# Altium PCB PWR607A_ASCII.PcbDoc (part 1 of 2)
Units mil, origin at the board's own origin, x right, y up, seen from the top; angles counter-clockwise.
Board outline 5200 x 2850 mil, 4 copper layers (Top Layer, MidLayer1, MidLayer2, Bottom Layer), stack 61.6 mil thick; 153 components, 65 nets, 324 pads, 227 vias.
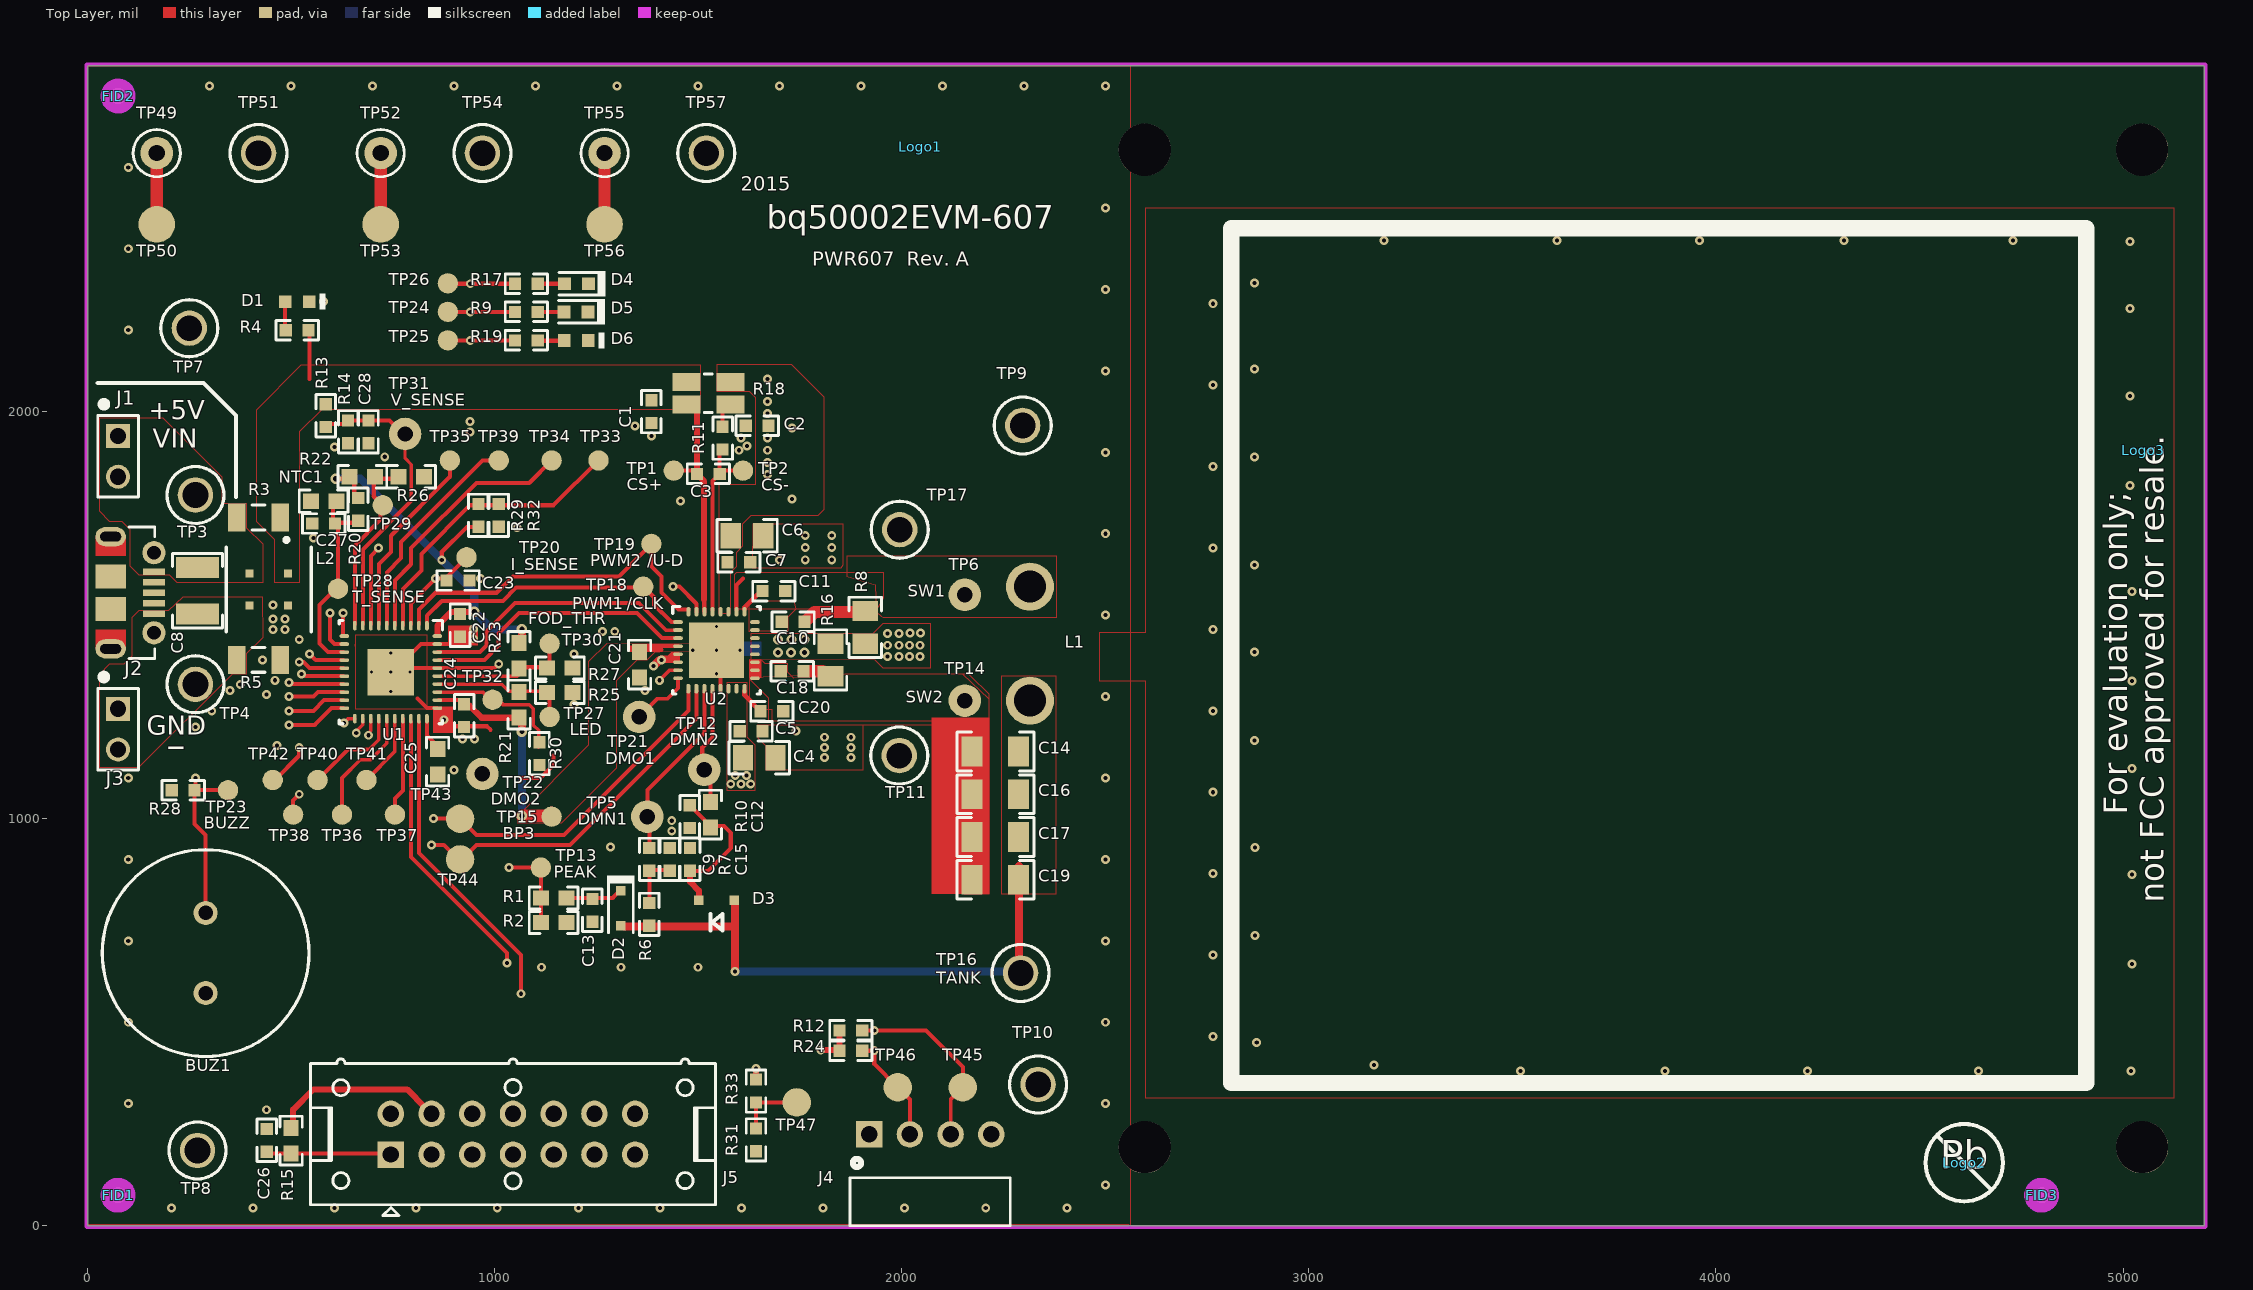
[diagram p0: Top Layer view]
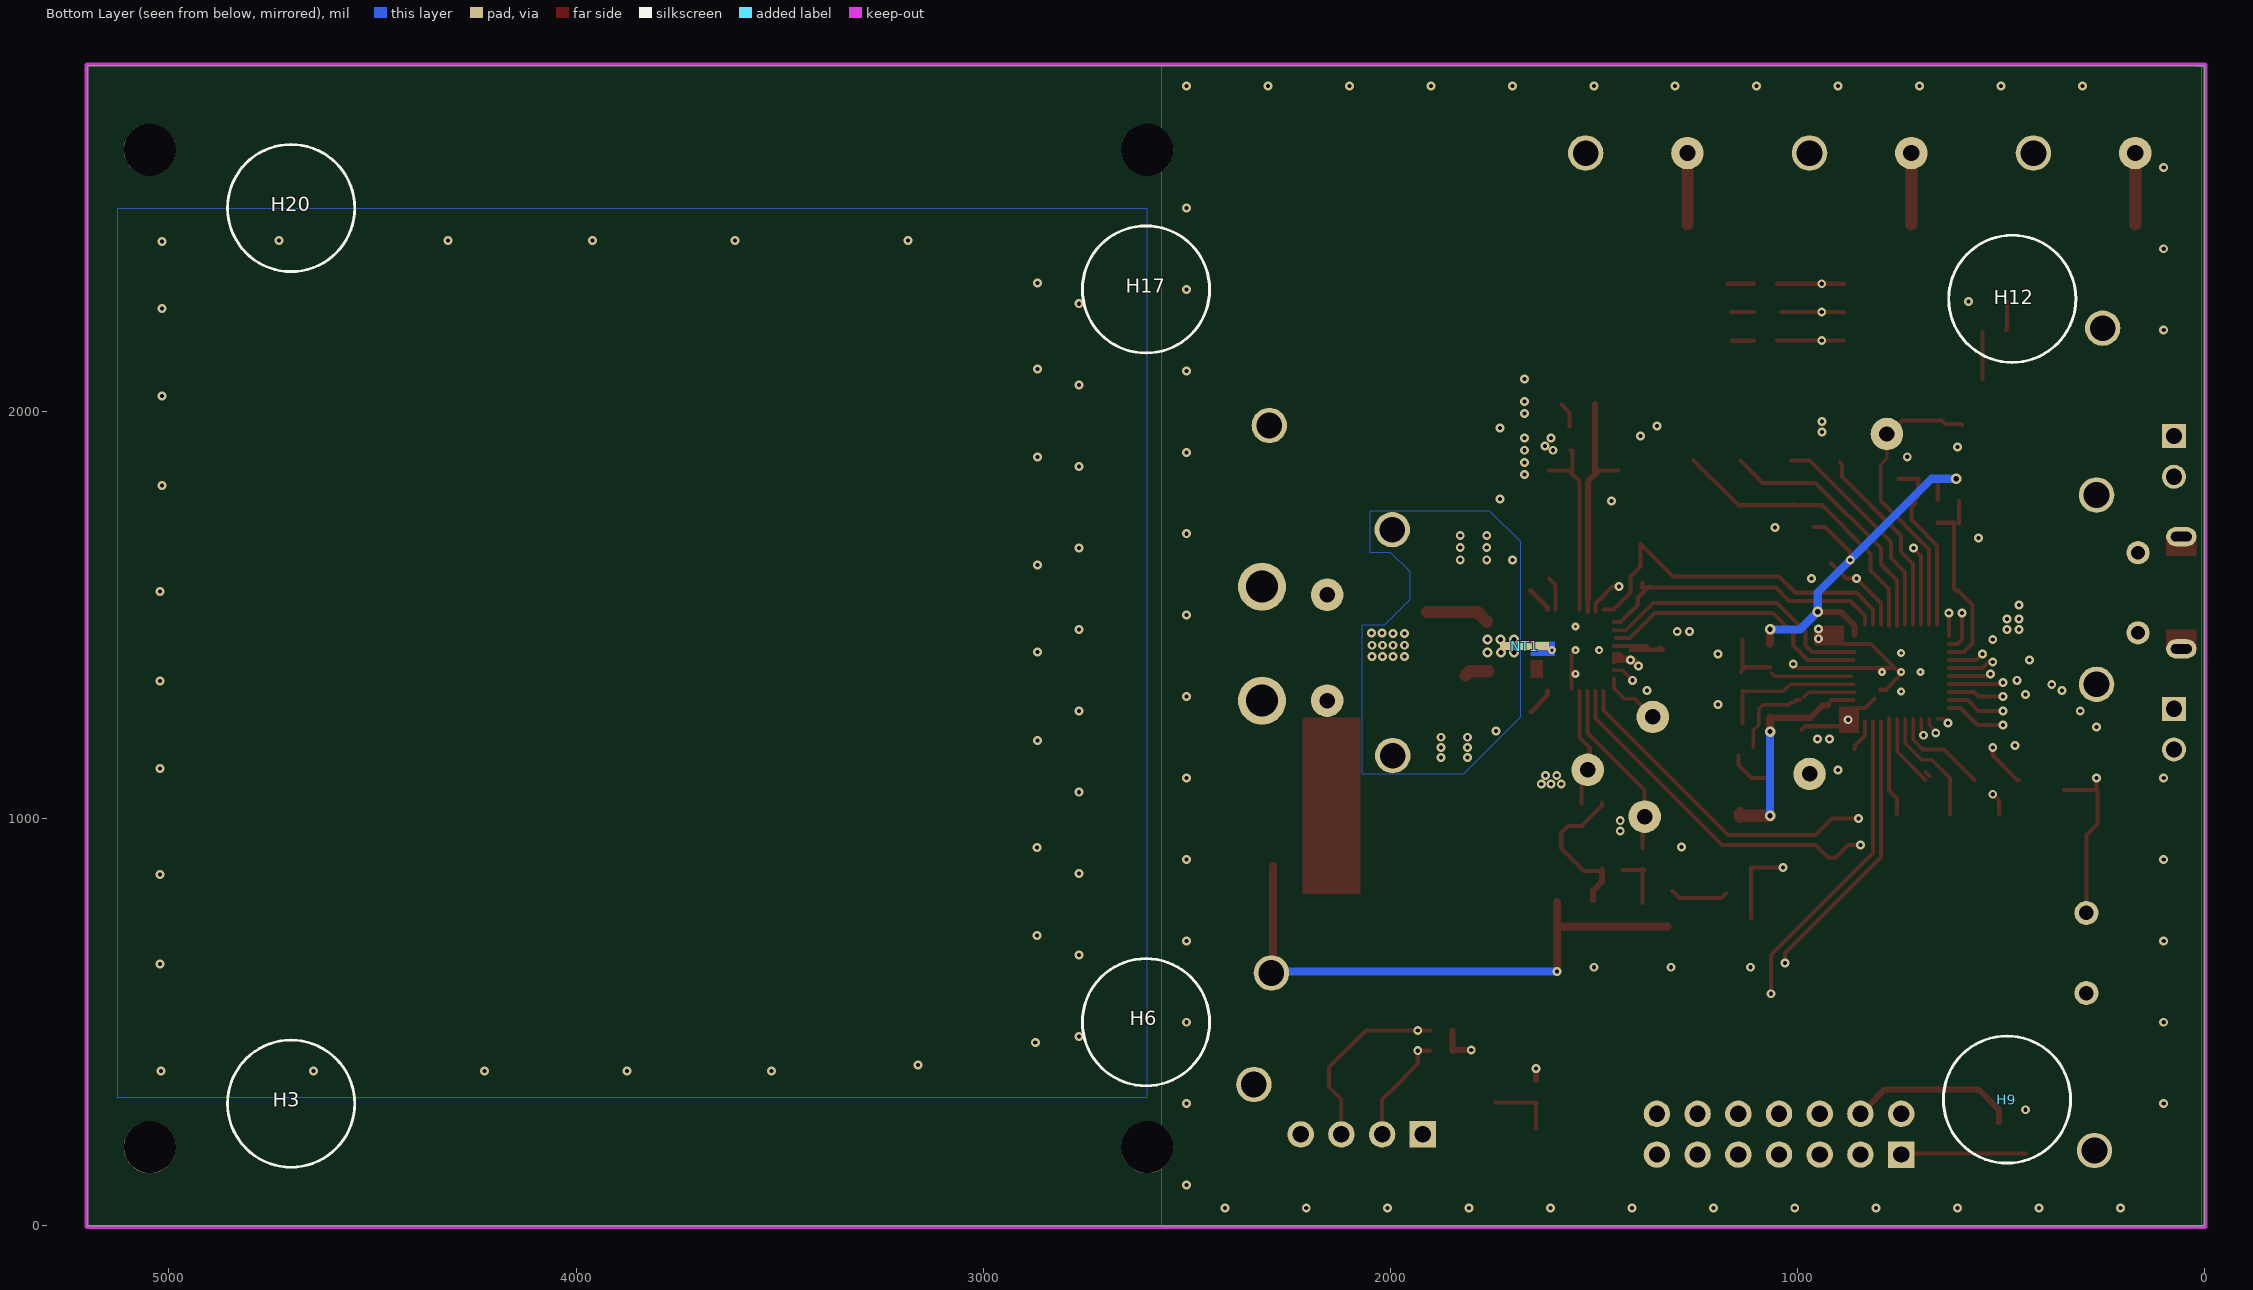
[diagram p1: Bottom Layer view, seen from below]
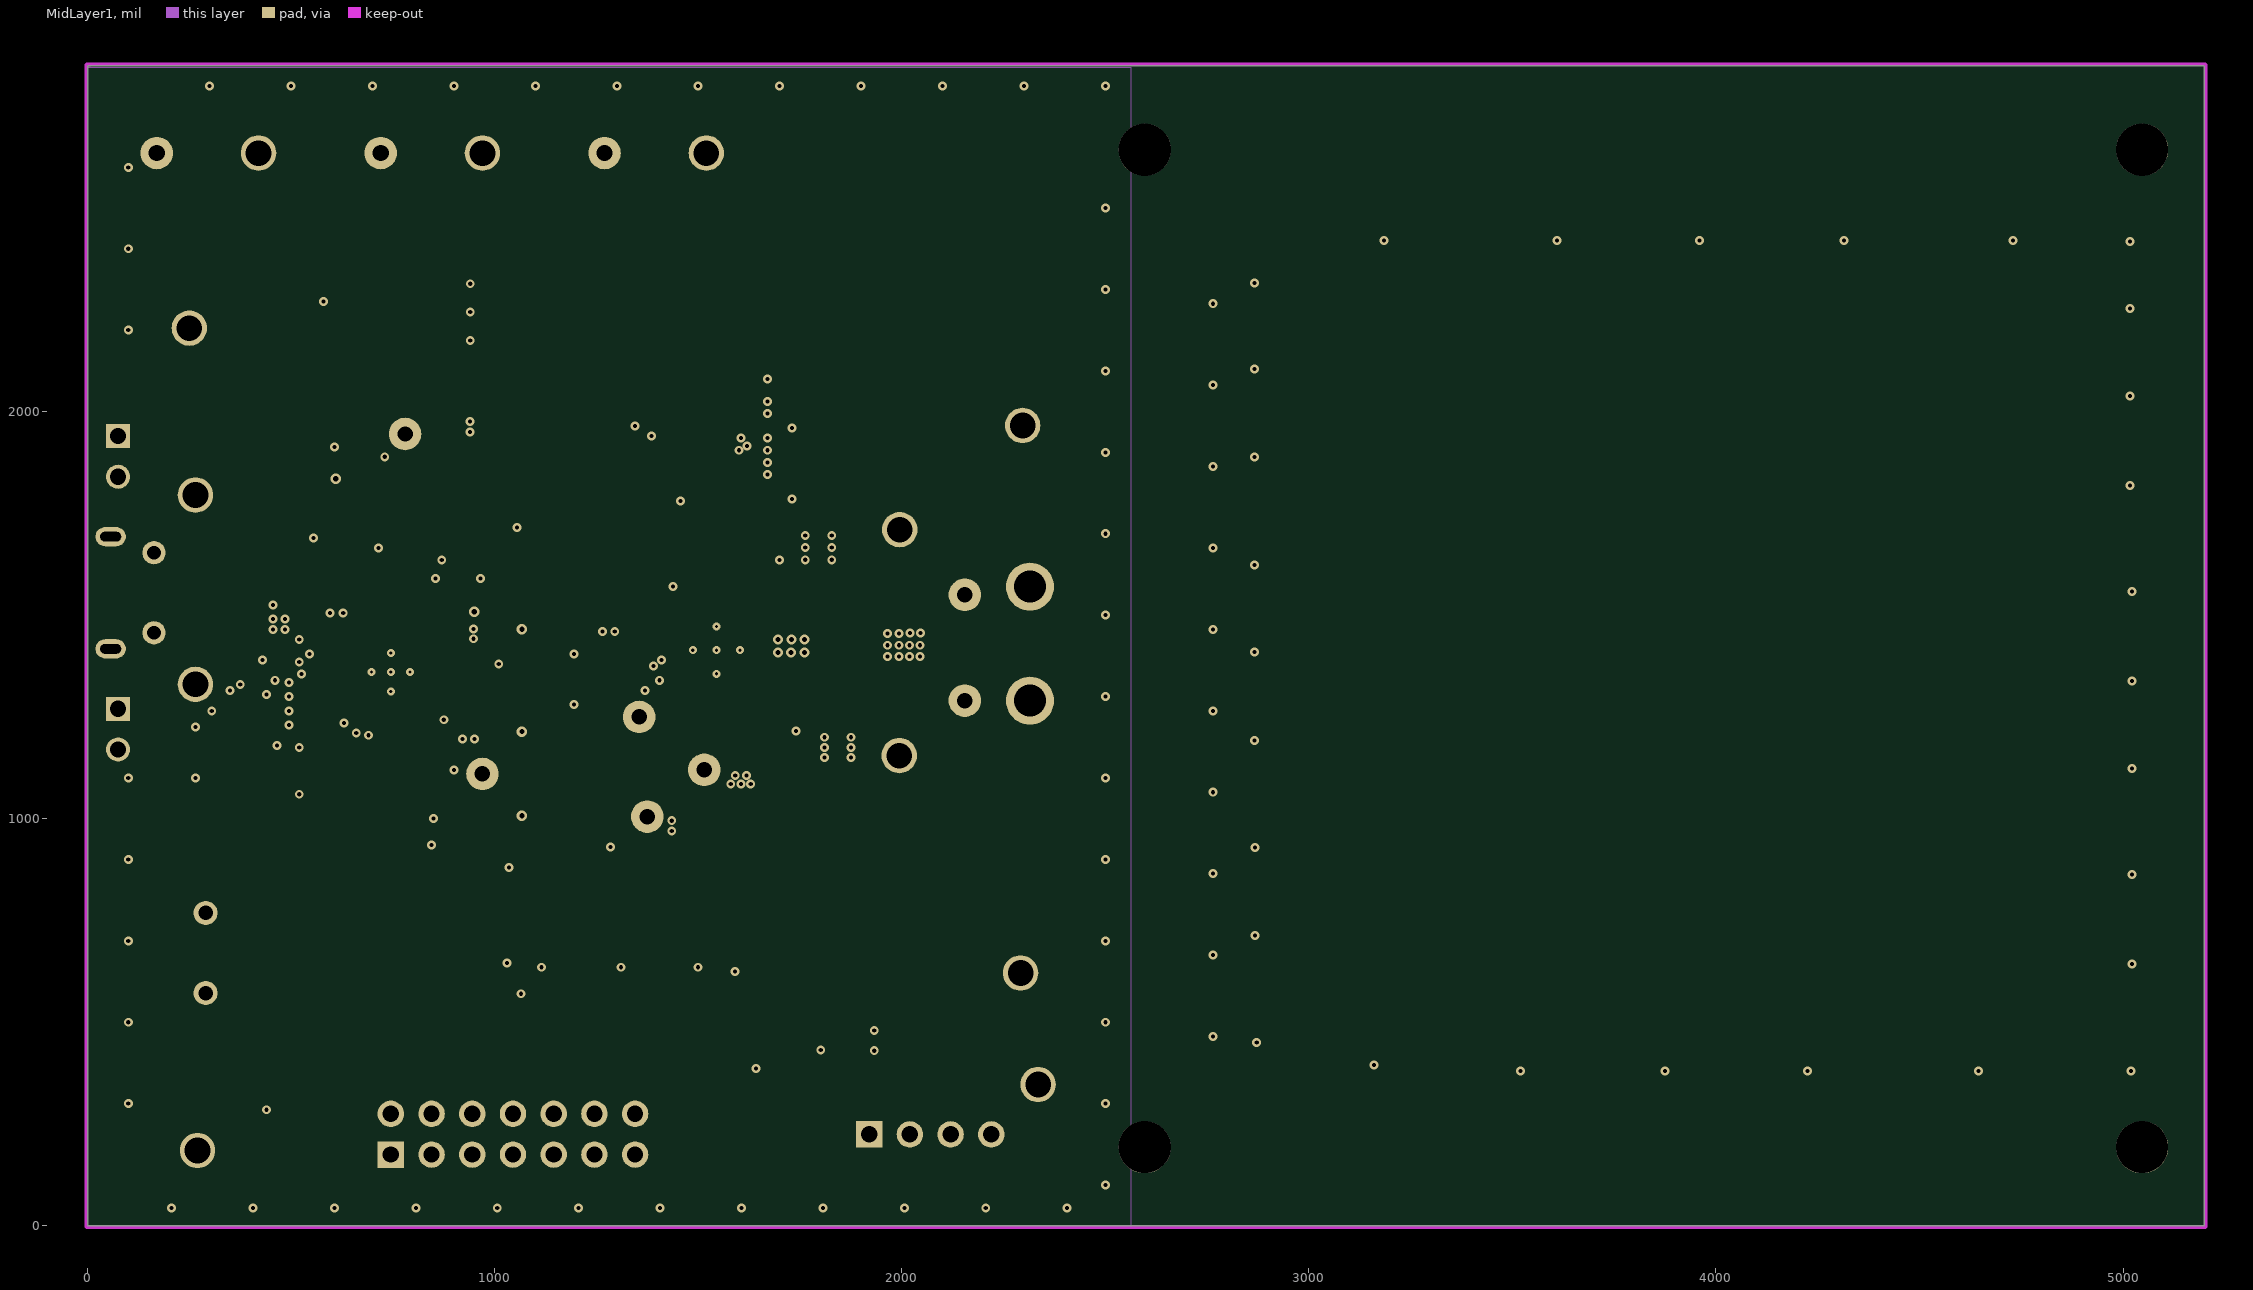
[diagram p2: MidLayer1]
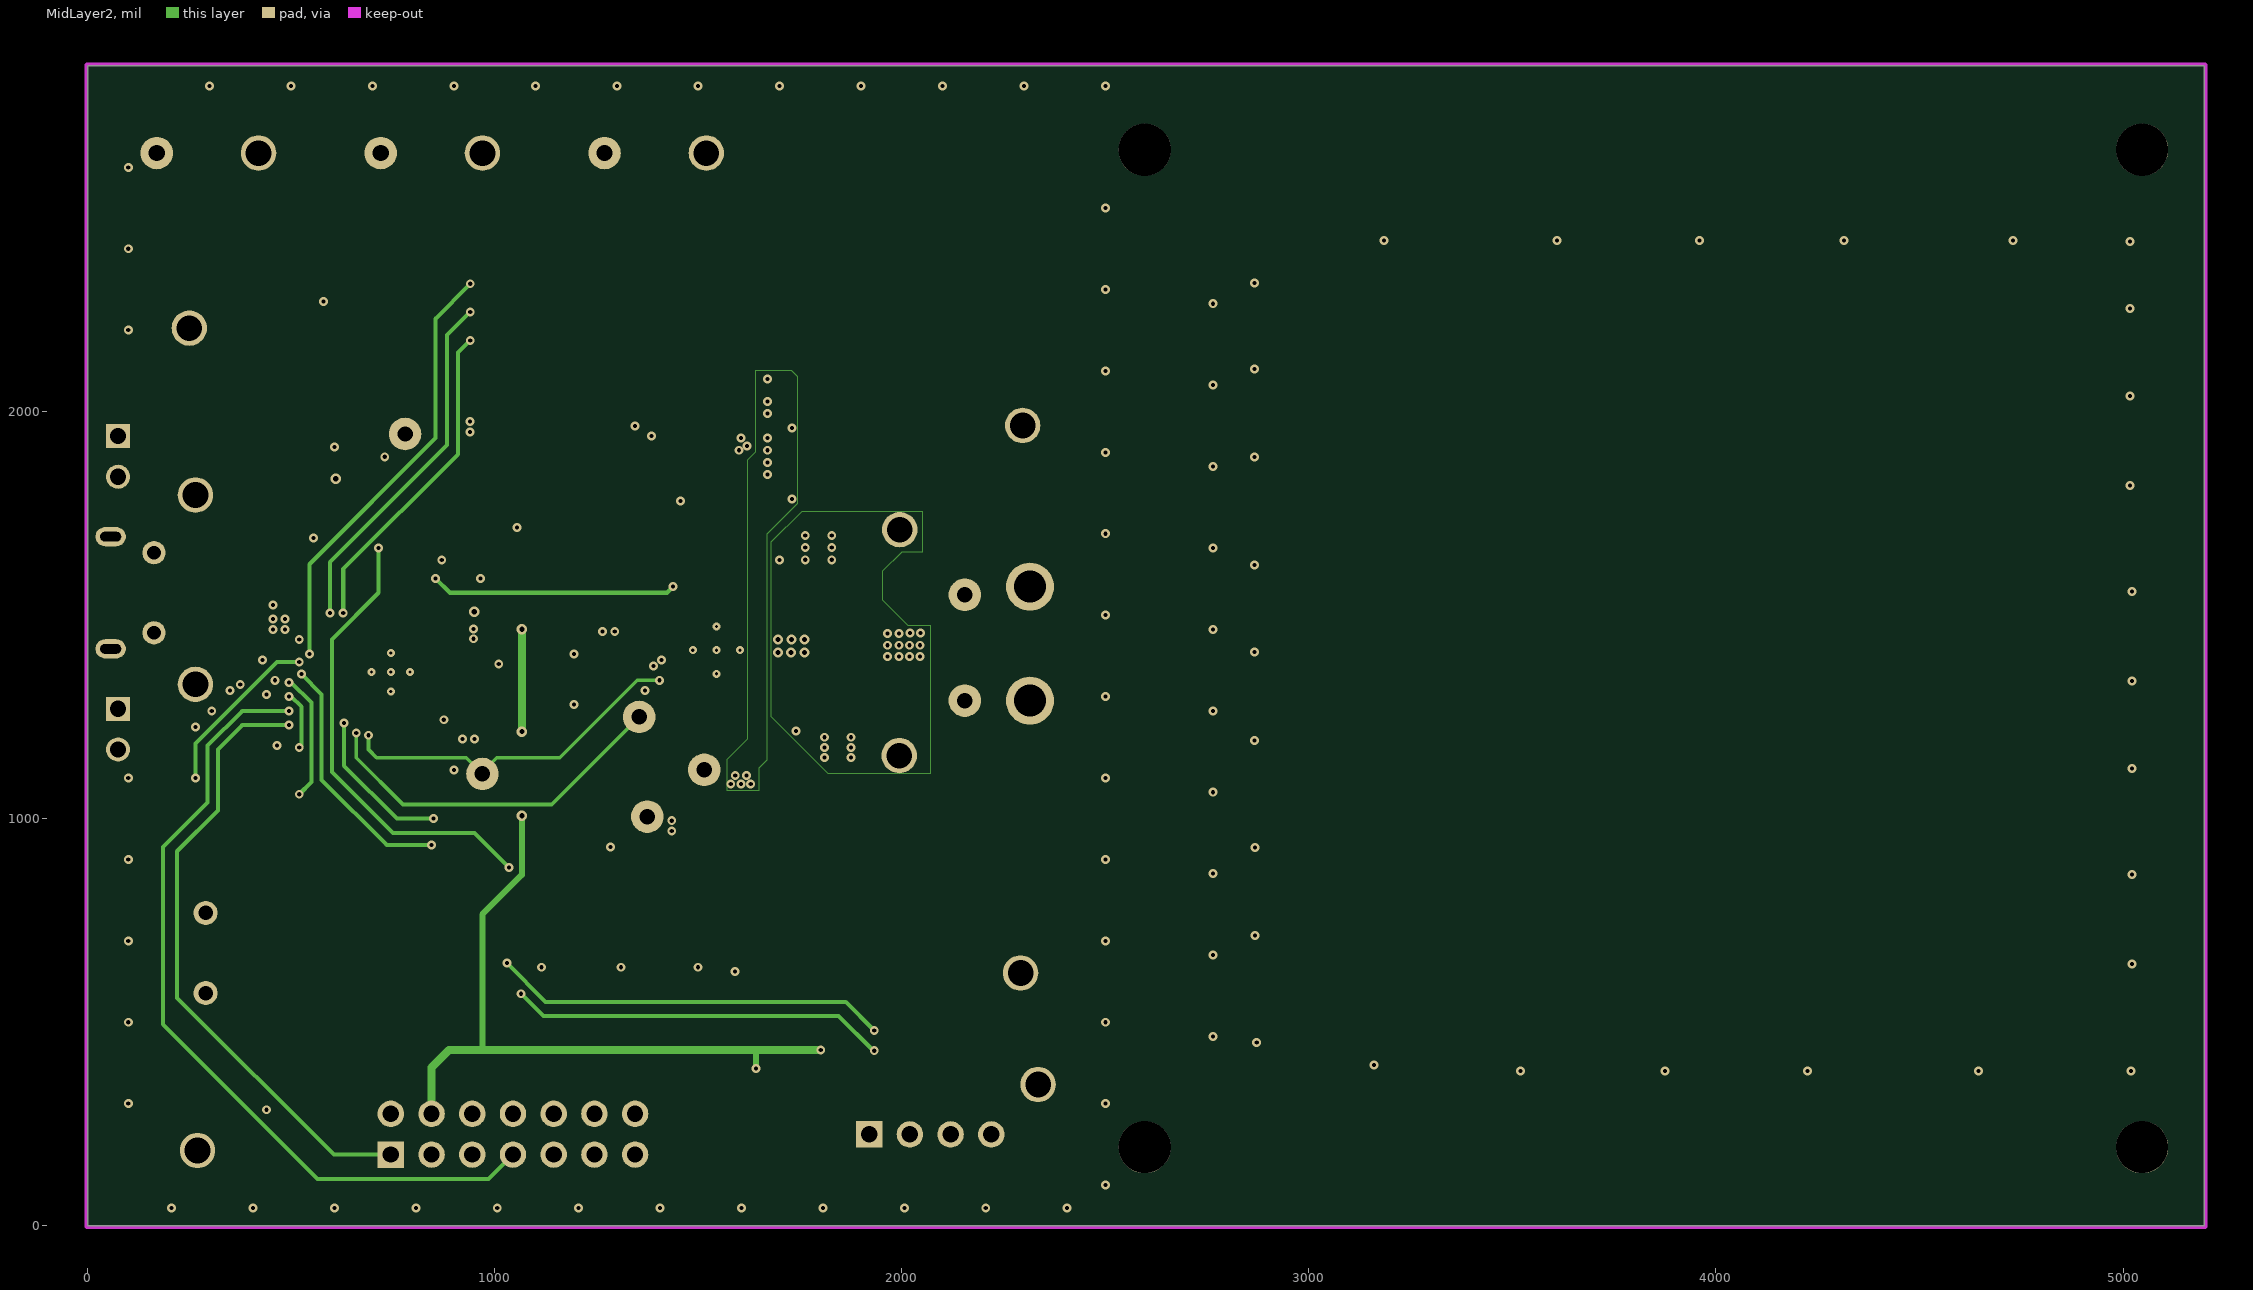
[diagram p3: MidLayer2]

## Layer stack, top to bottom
Top Solder: solder mask 0.4, Solder Resist, Dk 3.5
Top Layer: signal copper 1.4
Dielectric1: core 18, FR-4 High Tg, Dk 4.8
MidLayer1: signal copper 1.4
Dielectric2: prepreg 20, FR-4 High Tg, Dk 4.8
MidLayer2: signal copper 1.4
Dielectric3: core 18, FR-4 High Tg, Dk 4.8
Bottom Layer: signal copper 1.4
Bottom Solder: solder mask 0.4, Solder Resist, Dk 3.5

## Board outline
0,0 0,2850 5200,2850 5200,0

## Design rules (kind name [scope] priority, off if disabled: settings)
AcuteAngle [All] p0: scope1count=1 scope1_0_kind=Board scope1_0_value=Board scope2count=1 scope2_0_kind=Board scope2_0_value=Board commentlength=0 minimum=4.50000000000000E+0001
AcuteAngle [All] p1: minimum=4.50000000000000E+0001 checktracksonly=FALSE
AssemblyTestPointUsage [All] p0 off: scope1count=1 scope1_0_kind=Board scope1_0_value=Board scope2count=1 scope2_0_kind=Board scope2_0_value=Board commentlength=0
AssemblyTestPointUsage [All] p1 off: valid=2
AssemblyTestpoint [All] p0 off: scope1count=1 scope1_0_kind=Board scope1_0_value=Board scope2count=1 scope2_0_kind=Board scope2_0_value=Board commentlength=0
AssemblyTestpoint [All] p1 off: testpointundercomponent=TRUE minsize=40 maxsize=100 preferedsize=60 minholesize=0 maxholesize=40 preferedholesize=32 testpointgrid=1 usegrid=TRUE gridtolerance=0.01 allowsidetop=TRUE allowsidebottom=TRUE
Clearance Clearance_BoardEdge_MountingHoles [All] p0 off: scope1count=1 scope1_0_kind=Board scope1_0_value=Board scope2count=1 scope2_0_kind=Board scope2_0_value=Board commentlength=48 gap=40 // Protel DXP Scope 2 Expression Was: IsKeepOut
Clearance Clearance_BoardEdge_Poly [All] p0 off: scope1count=1 scope1_0_kind=Board scope1_0_value=Board scope2count=1 scope2_0_kind=Board scope2_0_value=Board commentlength=48 gap=25 // Protel DXP Scope 2 Expression Was: IsKeepOut
Clearance Clearance_BoardEdge [All] p0 off: scope1count=1 scope1_0_kind=Board scope1_0_value=Board scope2count=1 scope2_0_kind=Board scope2_0_value=Board commentlength=48 gap=25 // Protel DXP Scope 2 Expression Was: IsKeepOut
Clearance [All] p0: scope1count=1 scope1_0_kind=Board scope1_0_value=Board scope2count=1 scope2_0_kind=Board scope2_0_value=Board commentlength=0 gap=7.8
Clearance Clearance_Poly [All] p0 off: scope1count=1 scope1_0_kind=Board scope1_0_value=Board scope2count=1 scope2_0_kind=Board scope2_0_value=Board commentlength=48 gap=10 // Protel DXP Scope 1 Expression Was: InPolygon
Clearance Clearance_J1 [All] p0 off: scope1count=1 scope1_0_kind=Board scope1_0_value=Board scope2count=1 scope2_0_kind=Board scope2_0_value=Board commentlength=48 gap=15 // Protel DXP Scope 2 Expression Was: iskeepout
Clearance Clearance_GND_poly [All] p0 off: scope1count=1 scope1_0_kind=Board scope1_0_value=Board scope2count=1 scope2_0_kind=Board scope2_0_value=Board commentlength=62 gap=15 // Protel DXP Scope 1 Expression Was: inpoly and innet('GND')
Clearance Clearance_J1 [OnCopper and InComponent('J1') vs iskeepout] p1: gap=15
Clearance Clearance_BoardEdge_MountingHoles [OnCopper and InComponentClass('Mounting Holes') vs IsKeepOut] p2: gap=40
Clearance Clearance_BoardEdge_Poly [OnCopper and InPoly vs IsKeepOut] p3: gap=25
Clearance Clearance_BoardEdge [OnCopper and Not InComponentClass('Logo') and not InComponentClass('FiducialMark') and not InRegion(1000,500,4000,800) and Not IsKeepout vs IsKeepOut] p4: gap=25
Clearance Clearance_GND_poly [inpoly and innet('GND')] p5: gap=15
Clearance Clearance_Poly [InPolygon] p6: gap=10
Clearance [All] p7: gap=7.8
ComponentClearance ComponentClearance_Logo [All] p0 off: scope1count=1 scope1_0_kind=ComponentClass scope1_0_value=Logo scope2count=1 scope2_0_kind=Board scope2_0_value=Board commentlength=0 gap=50 collisioncheckmode=3
ComponentClearance ComponentClearance_ScrewToNut [All] p0 off: scope1count=1 scope1_0_kind=Board scope1_0_value=Board scope2count=1 scope2_0_kind=Board scope2_0_value=Board commentlength=71 gap=5 collisioncheckmode=3 // Protel DXP Scope 2 Expression Was: (HasFootprint('Keystone_1902C'))
ComponentClearance ComponentClearance_MountingHoles [All] p0 off: scope1count=1 scope1_0_kind=ComponentClass scope1_0_value="Mounting Holes" scope2count=1 scope2_0_kind=Board scope2_0_value=Board commentlength=0 gap=250 collisioncheckmode=3
ComponentClearance ComponentClearance_SmallPassives [All] p0 off: scope1count=1 scope1_0_kind=Board scope1_0_value=Board scope2count=1 scope2_0_kind=Board scope2_0_value=Board commentlength=508 gap=20 collisioncheckmode=3 // Protel DXP Scope 2 Expression Was: HasFootprint('0201*') or HasFootprint('0402*') or HasFootprint('0508') or HasFootprint('0603*') or HasFootprint('0612') or HasFootprint('0805*') or HasFootprint('0815*') or HasFootprint('0830*') or HasFootprint('1206*') or HasFootprint('1210*') or HasFootprint('1808*') or HasFootprint('1812*') or HasFootprint('1825*') or HasFootprint('2010*') or HasFootprint('2220*') or HasFootprint('2225*') or HasFootprint('2512*') or HasFootprint('2728*') or HasFootprint('3518*')
ComponentClearance ComponentClearance_THtoSMT [All] p0 off: scope1count=1 scope1_0_kind=Board scope1_0_value=Board scope2count=1 scope2_0_kind=Board scope2_0_value=Board commentlength=53 gap=100 collisioncheckmode=3 // Protel DXP Scope 2 Expression Was: IsSMTComponent
ComponentClearance ComponentClearance_THtoTH [All] p0 off: scope1count=1 scope1_0_kind=Board scope1_0_value=Board scope2count=1 scope2_0_kind=Board scope2_0_value=Board commentlength=54 gap=118.11 collisioncheckmode=3 // Protel DXP Scope 2 Expression Was: IsThruComponent
ComponentClearance [All] p0 off: scope1count=1 scope1_0_kind=Board scope1_0_value=Board scope2count=1 scope2_0_kind=Board scope2_0_value=Board commentlength=0 gap=40 collisioncheckmode=3
ComponentClearance ComponentClearance_Logo [InComponentClass('Logo')] p1 off: gap=50 collisioncheckmode=3 verticalgap=10 showdistances=FALSE
ComponentClearance ComponentClearance_ScrewToNut [(HasFootprint('NY PMS 440 0025 PH')) vs (HasFootprint('Keystone_1902C'))] p2 off: gap=5 collisioncheckmode=3 verticalgap=10 showdistances=FALSE
ComponentClearance ComponentClearance_MountingHoles [InComponentClass('Mounting Holes')] p3 off: gap=250 collisioncheckmode=3 verticalgap=100000 showdistances=FALSE
ComponentClearance ComponentClearance_SmallPassives [HasFootprint('0201*') or HasFootprint('0402*') or HasFootprint('0508') or HasFootprint('0603*') or HasFootprint('0612') or HasFootprint('0805*') or HasFootprint('0815*') or HasFootprint('0830*') or HasFootprint('1206*') or HasFootprint('1210*') or HasFootprint('1808*') or HasFootprint('1812*') or HasFootprint('1825*') or HasFootprint('2010*') or HasFootprint('2220*') or HasFootprint('2225*') or HasFootprint('2512*') or HasFootprint('2728*') or HasFootprint('3518*') vs HasFootprint('0201*') or HasFootprint('0402*') or HasFootprint('0508') or HasFootprint('0603*') or HasFootprint('0612') or HasFootprint('0805*') or HasFootprint('0815*') or HasFootprint('0830*') or HasFootprint('1206*') or HasFootprint('1210*') or HasFootprint('1808*') or HasFootprint('1812*') or HasFootprint('1825*') or HasFootprint('2010*') or HasFootprint('2220*') or HasFootprint('2225*') or HasFootprint('2512*') or HasFootprint('2728*') or HasFootprint('3518*')] p4 off: gap=20 collisioncheckmode=3 verticalgap=10 showdistances=FALSE
ComponentClearance ComponentClearance_THtoSMT [IsThruComponent vs IsSMTComponent] p5 off: gap=100 collisioncheckmode=3 verticalgap=30 showdistances=FALSE
ComponentClearance ComponentClearance_THtoTH [IsThruComponent vs IsThruComponent] p6 off: gap=118.11 collisioncheckmode=3 verticalgap=30 showdistances=FALSE
ComponentClearance [All] p7 off: gap=40 collisioncheckmode=3 verticalgap=10 showdistances=FALSE
DiffPairsRouting [All] p0: scope1count=1 scope1_0_kind=Board scope1_0_value=Board scope2count=1 scope2_0_kind=Board scope2_0_value=Board commentlength=0
DiffPairsRouting [All] p1: maxlimit=100 minlimit=10 mostfreqgap=10 toplayer_minwidth=15 toplayer_maxwidth=15 toplayer_prefwidth=15 midlayer1_minwidth=15 midlayer1_maxwidth=15 midlayer1_prefwidth=15 midlayer2_minwidth=15 midlayer2_maxwidth=15 midlayer2_prefwidth=15 bottomlayer_minwidth=15 bottomlayer_maxwidth=15 bottomlayer_prefwidth=15 maxuncoupledlength=1000
FabricationTestPointUsage TestPointUsage [All] p0 off: scope1count=1 scope1_0_kind=Board scope1_0_value=Board scope2count=1 scope2_0_kind=Board scope2_0_value=Board commentlength=0 valid=2 allowmultiple=FALSE
FabricationTestPointUsage TestPointUsage [All] p1 off: valid=2 allowmultiple=FALSE
FabricationTestpoint Testpoint [All] p0 off: scope1count=1 scope1_0_kind=Board scope1_0_value=Board scope2count=1 scope2_0_kind=Board scope2_0_value=Board commentlength=0 side=3 testpointundercomponent=TRUE minsize=40 maxsize=100 preferedsize=60 minholesize=0 maxholesize=40 preferedholesize=32 testpointgrid=1
FabricationTestpoint Testpoint [All] p1 off: side=3 testpointundercomponent=TRUE minsize=40 maxsize=100 preferedsize=60 minholesize=0 maxholesize=40 preferedholesize=32 testpointgrid=1 allowsidetop=TRUE allowsidebottom=TRUE usegrid=TRUE gridtolerance=0.01
FanoutControl Fanout_Small [All] p0 off: scope1count=1 scope1_0_kind=Board scope1_0_value=Board scope2count=1 scope2_0_kind=Board scope2_0_value=Board commentlength=84 // Protel DXP Scope 1 Expression Was: (CompPinCount < 5)   Fanout_Small (Default Rule)
FanoutControl Fanout_Default [All] p0: scope1count=1 scope1_0_kind=Board scope1_0_value=Board scope2count=1 scope2_0_kind=Board scope2_0_value=Board commentlength=30 // Fanout_Default (Default Rule)
FanoutControl Fanout_SOIC [All] p0 off: scope1count=1 scope1_0_kind=Board scope1_0_value=Board scope2count=1 scope2_0_kind=Board scope2_0_value=Board commentlength=71 // Protel DXP Scope 1 Expression Was: IsSOIC   Fanout_SOIC (Default Rule)
FanoutControl Fanout_BGA [All] p0 off: scope1count=1 scope1_0_kind=Board scope1_0_value=Board scope2count=1 scope2_0_kind=Board scope2_0_value=Board commentlength=69 // Protel DXP Scope 1 Expression Was: IsBGA   Fanout_BGA (Default Rule)
FanoutControl Fanout_LCC [All] p0 off: scope1count=1 scope1_0_kind=Board scope1_0_value=Board scope2count=1 scope2_0_kind=Board scope2_0_value=Board commentlength=69 // Protel DXP Scope 1 Expression Was: IsLCC   Fanout_LCC (Default Rule)
FanoutControl Fanout_LCC [IsLCC] p1: bgadir=Out bgaviamode=Centered fanoutstyle=Auto fanoutdirection=Alternating viagrid=1 // Fanout_LCC (Default Rule)
FanoutControl Fanout_BGA [IsBGA] p2: bgadir=Out bgaviamode=Centered fanoutstyle=Auto fanoutdirection=Alternating viagrid=1 // Fanout_BGA (Default Rule)
FanoutControl Fanout_Default [All] p4: bgadir=Out bgaviamode=Centered fanoutstyle=Auto fanoutdirection=Alternating viagrid=1 // Fanout_Default (Default Rule)
FanoutControl Fanout_Small [(CompPinCount < 5)] p5: bgadir=Out bgaviamode=Centered fanoutstyle=Auto fanoutdirection=OutThenIn viagrid=1 // Fanout_Small (Default Rule)
Height [All] p0: scope1count=1 scope1_0_kind=Board scope1_0_value=Board scope2count=1 scope2_0_kind=Board scope2_0_value=Board commentlength=0
HoleSize [All] p0: scope1count=1 scope1_0_kind=Board scope1_0_value=Board scope2count=1 scope2_0_kind=Board scope2_0_value=Board commentlength=0 absolutevalues=TRUE maxlimit=251 minlimit=7 maxpercent=80.000 minpercent=20.000
HoleSize [All] p1: absolutevalues=TRUE maxlimit=251 minlimit=7 maxpercent=80.000 minpercent=20.000
HoleToHoleClearance [All] p0: scope1count=1 scope1_0_kind=Board scope1_0_value=Board scope2count=1 scope2_0_kind=Board scope2_0_value=Board commentlength=0
LayerPairs [All] p0: scope1count=1 scope1_0_kind=Board scope1_0_value=Board scope2count=1 scope2_0_kind=Board scope2_0_value=Board commentlength=0 enforce=TRUE
MinimumAnnularRing [All] p0: scope1count=1 scope1_0_kind=Board scope1_0_value=Board scope2count=1 scope2_0_kind=Board scope2_0_value=Board commentlength=0 minimumring=5.9
MinimumAnnularRing [All] p1: minimumring=5.9
MinimumSolderMaskSliver MinimumSolderMaskSliver_Logo [All] p0: scope1count=1 scope1_0_kind=ComponentClass scope1_0_value=Logo scope2count=1 scope2_0_kind=ComponentClass scope2_0_value=Logo commentlength=0
MinimumSolderMaskSliver [All] p0: scope1count=1 scope1_0_kind=Board scope1_0_value=Board scope2count=1 scope2_0_kind=Board scope2_0_value=Board commentlength=0
MinimumSolderMaskSliver MinimumSolderMaskSliver_Logo [InComponentClass('Logo') vs InComponentClass('Logo')] p1: minsoldermaskwidth=0.7
MinimumSolderMaskSliver [All] p2: minsoldermaskwidth=3.97
NetAntennae [All] p0: scope1count=1 scope1_0_kind=Board scope1_0_value=Board scope2count=1 scope2_0_kind=Board scope2_0_value=Board commentlength=0
PasteMaskExpansion [All] p0: scope1count=1 scope1_0_kind=Board scope1_0_value=Board scope2count=1 scope2_0_kind=Board scope2_0_value=Board commentlength=0 expansion=0
PlaneClearance [All] p0: scope1count=1 scope1_0_kind=Board scope1_0_value=Board scope2count=1 scope2_0_kind=Board scope2_0_value=Board commentlength=0 clearance=10
PlaneClearance PlaneClearance_1 [All] p0 off: scope1count=1 scope1_0_kind=Board scope1_0_value=Board scope2count=1 scope2_0_kind=Board scope2_0_value=Board commentlength=71 clearance=20 // Protel DXP Scope 1 Expression Was: (InNet('TANK') AND InNet('GND'))
PlaneClearance PlaneClearance_1 [(InNet('TANK') AND InNet('GND'))] p1: clearance=20
PlaneClearance [All] p2: clearance=10
PlaneConnect [All] p0 off: scope1count=1 scope1_0_kind=Board scope1_0_value=Board scope2count=1 scope2_0_kind=Board scope2_0_value=Board commentlength=71 planeconnectstyle=Direct reliefexpansion=10 reliefentries=4 reliefconductorwidth=10 reliefairgap=10 // Protel DXP Scope 1 Expression Was: (InNet('GND') AND InNet('PGND'))
PlaneConnect [(InNet('GND') AND InNet('PGND'))] p1: planeconnectstyle=Direct reliefexpansion=10 reliefentries=4 reliefconductorwidth=10 reliefairgap=10
PolygonConnect [All] p0: scope1count=1 scope1_0_kind=Board scope1_0_value=Board scope2count=1 scope2_0_kind=Board scope2_0_value=Board commentlength=0 connectstyle=Direct reliefconductorwidth=10 reliefentries=4 polygonreliefangle="90 Angle"
PolygonConnect [All] p1: connectstyle=Direct reliefconductorwidth=10 reliefentries=4 polygonreliefangle="90 Angle" airgapwidth=10
RoutingCorners [All] p0: scope1count=1 scope1_0_kind=Board scope1_0_value=Board scope2count=1 scope2_0_kind=Board scope2_0_value=Board commentlength=0 cornerstyle=45-Degree minsetback=100 maxsetback=100
RoutingLayers [All] p0: scope1count=1 scope1_0_kind=Board scope1_0_value=Board scope2count=1 scope2_0_kind=Board scope2_0_value=Board commentlength=0 top layer=Automatic mid layer 1=Automatic mid layer 2=Automatic bottom layer=Automatic
RoutingPriority [All] p0: scope1count=1 scope1_0_kind=Board scope1_0_value=Board scope2count=1 scope2_0_kind=Board scope2_0_value=Board commentlength=0
RoutingTopology [All] p0: scope1count=1 scope1_0_kind=Board scope1_0_value=Board scope2count=1 scope2_0_kind=Board scope2_0_value=Board commentlength=0 topology=Shortest
RoutingVias [All] p0: scope1count=1 scope1_0_kind=Board scope1_0_value=Board scope2count=1 scope2_0_kind=Board scope2_0_value=Board commentlength=0 holewidth=10 width=22 viastyle="Through Hole" minholewidth=7.8 minwidth=19.6 maxholewidth=40 maxwidth=65
RoutingVias [All] p1: holewidth=10 width=22 viastyle="Through Hole" minholewidth=7.8 minwidth=19.6 maxholewidth=40 maxwidth=65
SMDToCorner [All] p0: scope1count=1 scope1_0_kind=Board scope1_0_value=Board scope2count=1 scope2_0_kind=Board scope2_0_value=Board commentlength=0 distance=30000
SMDToCorner [All] p1: distance=30000
ShortCircuit ShortCircuit_J1_fill [All] p0 off: scope1count=1 scope1_0_kind=Board scope1_0_value=Board scope2count=1 scope2_0_kind=Board scope2_0_value=Board commentlength=45 allowed=TRUE // Protel DXP Scope 2 Expression Was: isfill
ShortCircuit [All] p0: scope1count=1 scope1_0_kind=Board scope1_0_value=Board scope2count=1 scope2_0_kind=Board scope2_0_value=Board commentlength=0 allowed=FALSE
ShortCircuit ShortCircuit_J1_fill [ispad and incomponent('J2') vs isfill] p1: allowed=TRUE
ShortCircuit [All] p2: allowed=FALSE
SilkToBoardRegionClearance [All] p0 off: scope1count=1 scope1_0_kind=Board scope1_0_value=Board scope2count=1 scope2_0_kind=Board scope2_0_value=Board commentlength=0
SilkToBoardRegionClearance [All] p1 off:
SilkToSilkClearance [All] p0: scope1count=1 scope1_0_kind=Board scope1_0_value=Board scope2count=1 scope2_0_kind=Board scope2_0_value=Board commentlength=0
SilkToSilkClearance SilkToSilkClearance_logo [All] p0: scope1count=1 scope1_0_kind=ComponentClass scope1_0_value=Logo scope2count=1 scope2_0_kind=ComponentClass scope2_0_value=Logo commentlength=0
SilkToSilkClearance SilkToSilkClearance_logo [InComponentClass('Logo') vs InComponentClass('Logo')] p1: silktosilkclearance=0
SilkToSilkClearance [All] p2: silktosilkclearance=3
SilkToSolderMaskClearance SilkscreenOverComponentPads [All] p0 off: scope1count=1 scope1_0_kind=Board scope1_0_value=Board scope2count=1 scope2_0_kind=Board scope2_0_value=Board commentlength=44 // Protel DXP Scope 1 Expression Was: IsPad
SilkToSolderMaskClearance SilkscreenOverComponentPads [IsPad] p1: minsilkscreentomaskgap=3 clearancetoexposedcopper=TRUE
SolderMaskExpansion [All] p0: scope1count=1 scope1_0_kind=Board scope1_0_value=Board scope2count=1 scope2_0_kind=Board scope2_0_value=Board commentlength=0 expansion=1
SolderMaskExpansion [All] p1: expansion=1
UnRoutedNet [All] p0: scope1count=1 scope1_0_kind=Board scope1_0_value=Board scope2count=1 scope2_0_kind=Board scope2_0_value=Board commentlength=0
UnpouredPolygon [All] p0: scope1count=1 scope1_0_kind=Board scope1_0_value=Board scope2count=1 scope2_0_kind=Board scope2_0_value=Board commentlength=0
UnpouredPolygon [All] p1: allowunpoured=FALSE
Width [All] p0: scope1count=1 scope1_0_kind=Board scope1_0_value=Board scope2count=1 scope2_0_kind=Board scope2_0_value=Board commentlength=0 maxlimit=100 minlimit=8 preferedwidth=10
Width [All] p1: maxlimit=100 minlimit=8 preferedwidth=10 checkconnectedcopper=TRUE
11 further rules are at their usual default settings.

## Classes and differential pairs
component class PWR607A: BUZ1 C1 C2 C3 C4 C5 C6 C7 C8 C9 C10 C11 C12 C13 C14 C15 C16 C17 C18 C19 C20 C21 C22 C23 C24 C25 C26 C27 C28 D1 D2 D3 D4 D5 D6 J1 J2 J3 J4 J5 L1 L2 NT1 NTC1 R1 R2 R3 R4 R5 R6 R7 R8 R9 R10 R11 R12 R13 R14 R15 R16 R17 R18 R19 R20 R21 R22 R23 R24 R25 R26 R27 R28 R29 R30 R31 R32 R33 TP1 TP2 TP3 TP4 TP5 TP6 TP7 TP8 TP9 TP10 TP11 TP12 TP13 TP14 TP15 TP16 TP17 TP18 TP19 TP20 TP21 TP22 TP23 TP24 TP25 TP26 TP27 TP28 TP29 TP30 TP31 TP32 TP33 TP34 TP35 TP36 TP37 TP38 TP39 TP40 TP41 TP42 TP43 TP44 TP45 TP46 TP47 TP49 TP50 TP51 TP52 TP53 TP54 TP55 TP56 TP57 U1 U2
component class AssemblyNote: ZZ2 ZZ3 ZZ4
component class FiducialMark: FID1 FID2 FID3
component class Logo: Logo1 Logo2
component class PWR607A_Hardware: !PCB FID1 FID2 FID3 H1 H2 H3 H4 H5 H6 H7 H8 H9 H10 H11 H12 H13 H14 H15 H16 H17 H20 Logo1 Logo2 Logo3 ZZ2 ZZ3 ZZ4 ZZ5 ZZ6 ZZ7
component class Header: J1 J3

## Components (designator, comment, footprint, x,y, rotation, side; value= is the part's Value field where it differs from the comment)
BUZ1 "PS1240P02CT3" TDK_PS1240P02C 290,670 r270 top
C1 "GRM188R71E105KA12D" 0603_HV 1385,2000 r90 top
C2 "GRM188R71E105KA12D" 0603_HV 1645,1965 r0 top
C3 "GRM188R71A225KE15D" 0603_HV 1525,1847 r0 top
C4 "GRM21BR61E226ME44" 0805_HV 1650,1150 r0 top
C5 "C1608X7R1E104K" 0603_HV 1630,1215 r180 top
C6 "GRM21BR61E226ME44" 0805_HV 1620,1695 r0 top
C7 "C1608X7R1E104K" 0603_HV 1600,1630 r180 top
C8 "GRM32ER71E226KE15L" 1210 270,1560 r270 top
C9 "C1608C0G1H102J" 0603_HV 1380,900 r90 top
C10 "C1608X7R1H473K" 0603_HV 1733,1484 r0 top
C11 "C1608X7R1E104K" 0603_HV 1686,1559 r0 top
C12 "C1608X7R1H223K" 0603 1530,1010 r90 top
C13 "GRM188R71H222KA01D" 0603_HV 1240,775 r270 top
C14 "C3216C0G1E104J" 1206 2230,1165 r180 top
C15 "C1608C0G1H272J" 0603_HV 1480,900 r90 top
C16 "C3216C0G1E104J" 1206 2230,1060 r180 top
C17 "C3216C0G1E104J" 1206 2230,955 r180 top
C18 "C1608X7R1H473K" 0603_HV 1731,1362 r0 top
C19 "C3216C0G1E104J" 1206 2230,850 r180 top
C20 "C1608X7R1E104K" 0603_HV 1681,1264 r180 top
C21 "GRM188R61C225KE15D" 0603 1356,1378.5 r270 top
C22 "C1608X7R1E104K" 0603_HV 915,1475 r270 top
C23 "C1608X7R1E104K" 0603_HV 910,1585 r180 top
C24 "C1608X7R1E104K" 0603_HV 925,1253 r90 top
C25 "GRM188R71A474KA61D" 0603 860,1140 r90 top
C26 "C1608C0G1H102J" 0603_HV 440,210 r90 top
C27 "C1608X7R1E104K" 0603_HV 580,1725 r0 top
C28 "C1608X7R1E104K" 0603_HV 690,1950 r270 top
D1 "LTST-C190KGKT" LED_LTST-C190_G 515,2270 r0 top
D2 "MMDL914-TP" sod-323 1310,780 r270 top
D3 "MMDL914-TP" sod-323 1545,800 r0 top
D4 "LTST-C190KFKT" LED_LTST-C190 1201,2314 r0 top
D5 "LTST-C190CKT" LED_LTST-C190_Red 1200,2245 r0 top
D6 "LTST-C190KGKT" LED_LTST-C190_G 1200.47,2175 r0 top
FID1 "Fiducial" Fiducial10-20 75,75 r0 top
FID2 "Fiducial" Fiducial10-20 75,2775 r0 top
FID3 "Fiducial" Fiducial10-20 4800,75 r0 top
H3 "2563" Bumpon_SJ61A1 4700,300 r180 bottom
H6 "2563" Bumpon_SJ61A1 2600,500 r180 bottom
H9 "2563" Bumpon_SJ61A1 485,310 r180 bottom
H12 "2563" Bumpon_SJ61A1 472,2277 r180 bottom
H17 "2563" Bumpon_SJ61A1 2600,2300 r180 bottom
H20 "2563" Bumpon_SJ61A1 4700,2500 r180 bottom
J1 "PEC02SAAN" CONN_PEC02SAAN 75,1890 r270 top
J2 "105017-0001" CONN_105017-0001 110,1555 r270 top
J3 "PEC02SAAN" CONN_PEC02SAAN 75,1220 r270 top
J4 "22-05-3041" CONN_22-05-3041 2070,0 r0 top
J5 "SBH11-PBPC-D07-ST-BK" CONN_SBH11-PBPC-D07-ST-BK 1045,225 r0 top
L1 "760308111" WE-WPCC_5353_Qi_A11 3860,1405 r270 top locked
L2 "DLW5BTM102TQ2K" DLW5BT_TQ2 445,1562.71 r270 top
Logo1 "Texas Instruments" TI_Stacked_Overlay_Small 2045,2650 r0 top
Logo2 "Pb-Free Symbol" Pb-Free_Overlay_Medium 4610,155 r0 top
Logo3 "FCC disclaimer" FCC_disclaimer_stacked 5050,1905 r90 top
NT1 "Net-Tie" Net-Tie_20milWide_60milLong 1670,1424.13 r0 bottom net-tie
NTC1 "NTCG163JF103F" 0603 580,1780 r0 top
R1 "RG1608P-1133-B-T5" 0603 1145,805 r0 top
R2 "RG1608P-7682-B-T5" 0603 1145,745 r180 top
R3 "CRCW12060000Z0EA" 1206L 420,1740 r0 top
R4 "CRCW06031K00FKEA" 0603_HV 515,2200 r0 top
R5 "CRCW12060000Z0EA" 1206L 420,1390 r0 top
R6 "RC0603FR-0769K8L" 0603_HV 1380,765 r270 top
R7 "RC0603FR-0710KL" 0603_HV 1430,900 r270 top
R8 "ERJ-S6SJR20V" 0805_HV 1910,1470 r90 top
R9 "CRCW06031K00FKEA" 0603_HV 1078,2245 r180 top
R10 "RC0603FR-07499KL" 0603_HV 1479,1005 r90 top
R11 "CRCW06032R00FKEA" 0603_HV 1560,1935 r90 top
R12 "RC0603FR-0710KL" 0603_HV 1875,480 r180 top
R13 "RG1608P-7682-B-T5" 0603_HV 585,1990 r90 top
R14 "RT0603BRD0710KL" 0603_HV 640,1950 r90 top
R15 "RC0603JR-0747KL" 0603 500,209 r90 top
R16 "ERJ-S6SJR20V" 0805_HV 1825,1390 r270 top
R17 "CRCW06031K00FKEA" 0603_HV 1078,2314 r180 top
R18 "LVK12R020DER" LVK12 1525,2045 r0 top
R19 "CRCW06031K00FKEA" 0603_HV 1078,2175 r180 top
R20 "RC0603FR-0710KL" 0603_HV 665,1760 r270 top
R21 "RC0603FR-07100KL" 0603 1060,1280 r270 top
R22 "RC0603FR-07100KL" 0603 675,1840 r180 top
R23 "RC0603FR-07200KL" 0603 1060,1400 r90 top
R24 "RC0603FR-0710KL" 0603_HV 1875,430 r180 top
R25 "RC0603FR-0724K9L" 0603 1160,1310 r180 top
R26 "RC0603FR-0780K6L" 0603 795,1840 r180 top
R27 "RC0603FR-07100KL" 0603 1160,1370 r180 top
R28 "RC0603FR-0710KL" 0603_HV 235,1070 r0 top
R29 "RC0603FR-0710KL" 0603_HV 960,1745 r90 top
R30 "RC0603FR-0710KL" 0603_HV 1110,1160 r270 top
R31 "RC0603FR-0710KL" 0603_HV 1642,211 r270 top
R32 "RC0603FR-0710KL" 0603_HV 1010,1745 r90 top
R33 "RC0603FR-0710KL" 0603_HV 1642,331 r270 top
TP1 "Pogo Pad" PogoPad#1 1440,1855 r90 top
TP2 "Pogo Pad" PogoPad#1 1610,1855 r90 top
TP3 "5005" Keystone5005 265,1795 r0 top
TP4 "5011" Keystone5011 265,1330 r180 top
TP5 "PartNumber" TESTPOINT 1375,1005 r0 top
TP6 "PartNumber" TESTPOINT 2155,1550 r180 top
TP7 "5011" Keystone5011 250,2205 r0 top
TP8 "5011" Keystone5011 270,185 r0 top
TP9 "5011" Keystone5011 2297,1966 r0 top
TP10 "5011" Keystone5011 2335,347 r0 top
TP11 "5011" Keystone5011 1994,1155 r90 top
TP12 "PartNumber" TESTPOINT 1515,1120 r0 top
TP13 "Pogo Pad" PogoPad#1 1113.5,880 r0 top
TP14 "PartNumber" TESTPOINT 2155,1290 r90 top
TP15 "Pogo Pad" PogoPad#1 1140,1005 r90 top
TP16 "5007" Keystone5007 2292,621 r0 top
TP17 "5011" Keystone5011 1995,1710 r90 top
TP18 "Pogo Pad" PogoPad#1 1365,1570 r90 top
TP19 "Pogo Pad" PogoPad#1 1385,1675 r90 top
TP20 "Pogo Pad" PogoPad#1 931,1642 r0 top
TP21 "PartNumber" TESTPOINT 1355,1250 r0 top
TP22 "PartNumber" TESTPOINT 970,1110 r0 top
TP23 "Pogo Pad" PogoPad#1 345,1070 r0 top
TP24 "Pogo Pad" PogoPad#1 885,2245 r90 top
TP25 "Pogo Pad" PogoPad#1 885,2175 r90 top
TP26 "Pogo Pad" PogoPad#1 885,2315 r90 top
TP27 "Pogo Pad" PogoPad#1 1135,1250 r0 top
TP28 "Pogo Pad" PogoPad#1 615,1565 r0 top
TP29 "Pogo Pad" PogoPad#1 725,1770 r0 top
TP30 "Pogo Pad" PogoPad#1 1135,1430 r0 top
TP31 "PartNumber" TESTPOINT 780,1945 r0 top
TP32 "Pogo Pad" PogoPad#1 995,1292 r90 top
TP33 "Pogo Pad" PogoPad#1 1255,1880 r90 top
TP34 "Pogo Pad" PogoPad#1 1140,1880 r0 top
TP35 "Pogo Pad" PogoPad#1 890,1880 r0 top
TP36 "Pogo Pad" PogoPad#1 625,1010 r0 top
TP37 "Pogo Pad" PogoPad#1 755,1010 r0 top
TP38 "Pogo Pad" PogoPad#1 505,1010 r90 top
TP39 "Pogo Pad" PogoPad#1 1010,1880 r0 top
TP40 "Pogo Pad" PogoPad#1 565,1095 r0 top
TP41 "Pogo Pad" PogoPad#1 685,1095 r0 top
TP42 "Pogo Pad" PogoPad#1 455,1095 r90 top
TP43 "Pogo Pad" PogoPad#2 915,1000 r90 top
TP44 "Pogo Pad" PogoPad#2 915,900 r90 top
TP45 "Pogo Pad" PogoPad#2 2150,340 r90 top
TP46 "Pogo Pad" PogoPad#2 1990,340 r90 top
TP47 "Pogo Pad" PogoPad#2 1742,303 r90 top
TP49 "5002" Keystone5002 170,2635 r90 top
TP50 "Pogo Pad" PogoPad#3 170,2460 r90 top locked
TP51 "5011" Keystone5011 420,2635 r0 top
TP52 "5002" Keystone5002 720,2635 r90 top
TP53 "Pogo Pad" PogoPad#3 720,2460 r90 top locked
TP54 "5011" Keystone5011 970,2635 r0 top
TP55 "5002" Keystone5002 1270,2635 r90 top
TP56 "Pogo Pad" PogoPad#3 1270,2460 r0 top locked
TP57 "5011" Keystone5011 1520,2635 r0 top
U1 "BQ500511RHAR" RHA0040A 745,1360 r270 top
U2 "BQ50002RHB" RHB0032E 1544.9,1413.9 r0 top
ZZ2 "These assemblies are ESD sensitive, ESD precautions shall be observed." AssemblyNote 200,3517 r0 top
ZZ3 "These assemblies must be clean and free from flux and all contaminants. Use of no clean flux is not acceptable." AssemblyNote 200,3430 r0 top
ZZ4 "These assemblies must comply with workmanship standards IPC-A-610 Class 2., unless otherwise specified." AssemblyNote 200,3350 r0 top
ZZ5 "If Sil-Pad part number GP1500-0.020-00-0404 is used, the pads need to be cut into 2 inch squares." AssemblyNote 200,3265 r0 top
ZZ6 "Apply thin layer of SA-1000 between Aluminum Plate MCH003 and PCB during installation" AssemblyNote 200,3185 r0 top
ZZ7 "See PWR045 Assembly Guide for build up on L1 and associated hardware" AssemblyNote 200,3105 r0 top

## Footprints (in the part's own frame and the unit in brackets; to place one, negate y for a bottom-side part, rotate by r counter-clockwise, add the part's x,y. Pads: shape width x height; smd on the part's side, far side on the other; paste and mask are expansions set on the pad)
0603 [mm] "0603 from SM-752 data"
  rect 1x0.95 smd: 1(-0.8,0) 2(0.8,0)
  silkscreen extent -1.52,-0.69 1.52,0.69
0603_HV [mil] "Ernesto recommended land pattern.  26 mil between pads."
  rect 30x30 smd: 1(-28,0) 2(28,0)
  silkscreen extent -52,-24 52,24
0805_HV [mil] "0805 with 30mil clearance between pads"
  rect 50x63 smd: 1(-40,0) 2(40,0)
  silkscreen extent -74,-40 74,40
1206 [mm] "1206 from SM-752 data"
  rect 1.3x1.85 smd: 1(-1.45,0) 2(1.45,0)
  silkscreen extent -2.4,-1.21 2.4,1.21
1206L [mm] "1206 from SM-752 data"
  rect 1.1x1.75 smd: 1(-1.35,0) 2(1.35,0)
  silkscreen extent -0.4,-0.77 0.4,0.77
1210 [mm] "1210 from SM-752 data"
  rect 1.3x2.7 smd: 1(-1.45,0) 2(1.45,0)
  silkscreen extent -2.32,-1.57 2.32,1.57
AssemblyNote [mil] "Assembly Note"
Bumpon_SJ61A1 [mil] "3M Cylindrical Bumpon black"
  round 1 on Mech4: 0(0,0)
  silkscreen extent -156,-156 156,156
CONN_22-05-3041 [mm] "MOLEX"
  rect 1.65x1.65 hole 1.02: 1(-3.81,5.7)
  round 1.65 hole 1.02: 2(-1.27,5.7) 3(1.27,5.7) 4(3.81,5.7)
  silkscreen extent -5,0 5,4.18
CONN_105017-0001 [mm] "Molex Micro USB-B"
  rect 0.4x1.35 smd mask+0.051: 1(-1.3,1.35) 2(-0.65,1.35) 3(0,1.35) 4(0.65,1.35) 5(1.3,1.35)
  oval 1.2x1.9 hole 0.6 slot 1.3 at 90 deg: 6(-3.5,-1.35) 9(3.5,-1.35)
  rect 1.5x1.9 smd: 7(-1,-1.35) 8(1,-1.35)
  round 1.45 hole 0.85: 10(2.5,1.35) 11(-2.5,1.35)
  Top Layer region: -3.5,-2.3 -2.3,-2.3 -2.3,-0.4 -3.5,-0.4
  Top Layer region: 3.5,-0.4 2.3,-0.4 2.3,-2.3 3.5,-2.3
  silkscreen extent -4.1,-0.2 4.1,1.4
CONN_PEC02SAAN [mm] "SULLINS"
  rect 1.5x1.5 hole 1.016: 1(-1.27,0)
  round 1.5 hole 1.016: 2(1.27,0)
  silkscreen extent -3.45,-1.27 2.54,1.27
CONN_SBH11-PBPC-D07-ST-BK [mm] "Sullins recommended land pattern"
  rect 1.65x1.65 hole 1.016 mask+0: 1(-7.62,-1.27)
  round 1.65 hole 1.016 mask+0: 2(-7.62,1.27) 3(-5.08,-1.27) 4(-5.08,1.27) 5(-2.54,-1.27) 6(-2.54,1.27) 7(0,-1.27) 8(0,1.27) 9(2.54,-1.27) 10(2.54,1.27) 11(5.08,-1.27) 12(5.08,1.27) 13(7.62,-1.27) 14(7.62,1.27)
  silkscreen extent -12.64,-5.08 12.64,4.7
DLW5BT_TQ2 [mm] "SMD, 4-Leads, Body 5x5mm"
  rect 0.5x0.5 smd: 1(-1,1.2) 2(-1,-1.2) 3(1,-1.2) 4(1,1.2)
  silkscreen extent -3.22,-2.65 2.65,2.65
FCC_disclaimer_stacked [mil]
Fiducial10-20 [mm]
  round 1 smd mask+0.5: 1(0,0)
  Top Layer keep-out circle w1.178: c0,0 r0.5
Keystone5002 [mil] "For Keystone 500x miniature loop terminals"
  round 80 hole 40: 1(0,0)
  silkscreen extent -58,-58 58,58
Keystone5005 [mil] "Keystone Compact loops"
  round 87 hole 63: 1(0,0)
  silkscreen extent -70,-70 70,70
Keystone5007 [mil] "Keystone Compact loops"
  round 87 hole 63: 1(0,0)
  silkscreen extent -70,-70 70,70
Keystone5011 [mil] "Keystone Multipurpose loops"
  round 87 hole 63: 1(0,0)
  silkscreen extent -70,-70 70,70
LED_LTST-C190 [mm] "Lite-On"
  rect 0.8x0.8 smd: 1(-0.75,0) 2(0.75,0)
  silkscreen extent -1.1,-0.8 1.8,0.8
LED_LTST-C190_G [mm] "Lite-On"
  rect 0.8x0.8 smd: 1(-0.75,0) 2(0.75,0)
  silkscreen extent 1.37,-0.5 1.75,0.5
LED_LTST-C190_Red [mm] "Lite-On"
  rect 0.8x0.8 smd: 1(-0.75,0) 2(0.75,0)
  silkscreen extent -1.1,-0.8 1.8,0.8
LVK12 [mm] "Ohmite"
  rect 1.75x1.1 smd: 1(-1.375,0.7) 2(1.375,0.7) 3(-1.375,-0.7) 4(1.375,-0.7)
  silkscreen extent -0.25,-1.2 0.25,1.2
Net-Tie_20milWide_60milLong [mil] "20mil net tie, no solder mask opening, no solder paste"
  rect 60x20 smd paste-10 mask-10: 1(-30,0) 2(30,0)
Pb-Free_Overlay_Medium [mil]
  silkscreen extent -95,-95 95,95
PogoPad#1 [mil] "No Solder Paste"
  round 50 smd paste-35: 1(0,0)
PogoPad#2 [mil] "No Solder Paste"
  round 70 smd paste-35: 1(0,0)
PogoPad#3 [mil] "No Solder Paste"
  round 90 smd paste-45: 1(0,0)
RHA0040A [mm] "QFN, 40-Leads, Body 6x6mm, Pitch 0.5mm, Thermal Pad 2.9x2.9mm, TI Recommended"
  oval 0.6x0.23 smd mask+0.07: 1(-2.9,2.25) 2(-2.9,1.75) 3(-2.9,1.25) 4(-2.9,0.75) 5(-2.9,0.25) 6(-2.9,-0.25) 7(-2.9,-0.75) 8(-2.9,-1.25) 9(-2.9,-1.75) 10(-2.9,-2.25) 21(2.9,-2.25) 22(2.9,-1.75) 23(2.9,-1.25) 24(2.9,-0.75) 25(2.9,-0.25) 26(2.9,0.25) 27(2.9,0.75) 28(2.9,1.25) 29(2.9,1.75) 30(2.9,2.25)
  oval 0.23x0.6 smd mask+0.07: 11(-2.25,-2.9) 12(-1.75,-2.9) 13(-1.25,-2.9) 14(-0.75,-2.9) 15(-0.25,-2.9) 16(0.25,-2.9) 17(0.75,-2.9) 18(1.25,-2.9) 19(1.75,-2.9) 20(2.25,-2.9) 31(2.25,2.9) 32(1.75,2.9) 33(1.25,2.9) 34(0.75,2.9) 35(0.25,2.9) 36(-0.25,2.9) 37(-0.75,2.9) 38(-1.25,2.9) 39(-1.75,2.9) 40(-2.25,2.9)
  rect 2.9x2.9 smd paste-2.45: 41(0,0)
  silkscreen extent -3.22,-3.22 3.22,3.22
RHB0032E [mm] "QFN, 32-Leads, Body 5x5mm, Pitch 0.5mm, Thermal Pad 3.45x3.45mm, TI Recommended"
  oval 0.6x0.24 smd: 1(-2.4,1.75) 2(-2.4,1.25) 3(-2.4,0.75) 4(-2.4,0.25) 5(-2.4,-0.25) 6(-2.4,-0.75) 7(-2.4,-1.25) 8(-2.4,-1.75) 17(2.4,-1.75) 18(2.4,-1.25) 19(2.4,-0.75) 20(2.4,-0.25) 21(2.4,0.25) 22(2.4,0.75) 23(2.4,1.25) 24(2.4,1.75)
  oval 0.24x0.6 smd: 9(-1.75,-2.4) 10(-1.25,-2.4) 11(-0.75,-2.4) 12(-0.25,-2.4) 13(0.25,-2.4) 14(0.75,-2.4) 15(1.25,-2.4) 16(1.75,-2.4) 25(1.75,2.4) 26(1.25,2.4) 27(0.75,2.4) 28(0.25,2.4) 29(-0.25,2.4) 30(-0.75,2.4) 31(-1.25,2.4) 32(-1.75,2.4)
  rect 3.45x3.45 smd paste-1.725: 33(0,0)
  silkscreen extent -2.72,-2.73 2.72,2.73
sod-323 [mm] "NXP recommended land pattern"
  rect 0.6x0.6 smd paste-0.05: 1(-1.1,0) 2(1.1,0)
  silkscreen extent -2.06,-0.86 1.53,0.86
TDK_PS1240P02C [mm] "TDK"
  round 1.5 hole 0.9: 1(-2.5,0) 2(2.5,0)
  silkscreen extent -6.45,-6.45 6.45,6.45
TESTPOINT [mil]
  round 80 hole 37.99: 1(0,0)
TI_Stacked_Overlay_Small [mil]
WE-WPCC_5353_Qi_A11 [mm] "WURTH"
  round 3 hole 2: 1(-4.191,-39.243) 2(2.921,-39.243)

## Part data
BUZ1: "Buzzer, Piezo, 4kHz, 12.2mm, TH"
C1 C2: "CAP, CERM, 1 µF, 25 V, +/- 10%, X7R, 0603"
C3: "CAP, CERM, 2.2 µF, 10 V, +/- 10%, X7R, 0603"
C4 C6: "CAP, CERM, 22uF, 25V, +/-20%, X5R, 0805"
C5 C7 C11 C20 C22 C23 C24 C27 C28: "CAP, CERM, 0.1uF, 25V, +/-10%, X7R, 0603"
C8: "CAP, CERM, 22uF, 25V, +/-10%, X7R, 1210"
C9 C26: "CAP, CERM, 1000pF, 50V, +/-5%, C0G/NP0, 0603"
C10 C18: "CAP, CERM, 0.047uF, 50V, +/-10%, X7R, 0603"
C12: "CAP, CERM, 0.022 µF, 50 V, +/- 10%, X7R, 0603"
C13: "CAP, CERM, 2200 pF, 50 V, +/- 10%, X7R, 0603"
C14 C16 C17 C19: "CAP, CERM, 0.1 µF, 25 V, +/- 5%, C0G/NP0, 1206"
C15: "CAP, CERM, 2700pF, 50V, +/-5%, C0G/NP0, 0603"
C21: "CAP, CERM, 2.2uF, 16V, +/-10%, X5R, 0603"
C25: "CAP, CERM, 0.47uF, 10V, +/-10%, X7R, 0603"
D1 D6: "LED, Green, SMD"
D2 D3: "Diode, Switching, 100V, 0.2A, SOD-323"
D4: "LED, Orange, SMD"
D5: "LED, Red, SMD"
FID1 FID2 FID3: "Fiducial mark.  There is nothing to buy or mount."
H3 H6 H9 H12 H17 H20: library part SJ61A1, "Mounting Feet, 0.25\" tall"
J1 J3: "Header, 100mil, 2x1, Tin, TH"
J2: "Receptacle, Micro-USB-B, Right Angle, SMD"
J4: "Header (friction lock), 100mil, 4x1, R/A, TH"
J5: "Header (shrouded), 100 mil, 7x2, Gold plated, TH"
L1: "Inductor, 6.3 µH, 13 A, 0.017 ohm, TH"
L2: "Coupled inductor, 2.5 A, 0.034 ohm, SMD"
Logo1: library part TI_Logo, "Texas Instrument Corporate Signature"
Logo2: library part Pb-Free
Logo3: library part FCC_disclaimer, "FCC_disclaimer"
NT1: "Single point connection between nets."
NTC1: "Thermistor NTC, 10.0k ohm, 1%, 0603"
R1: "RES, 113 k, 0.1%, 0.1 W, 0603"
R2 R13: "RES, 76.8 k, 0.1%, 0.1 W, 0603"
R3 R5: "RES, 0 ohm, 5%, 0.25W, 1206"
R4 R9 R17 R19: "RES, 1.00 k, 1%, 0.1 W, 0603"
R6: "RES, 69.8k ohm, 1%, 0.1W, 0603"
R7 R12 R20 R24 R28 R29 R30 R31 R32 R33: "RES, 10.0k ohm, 1%, 0.1W, 0603"
R8 R16: library part CRM0805-FX-R510ELF, "RES, 0.2 ohm, 5%, 0.25W, 0805"
R10: "RES, 499k ohm, 1%, 0.1W, 0603"
R11: "RES, 2.00, 1%, 0.1 W, 0603"
R14: "RES, 10.0 k, 0.1%, 0.1 W, 0603"
R15: "RES, 47k ohm, 5%, 0.1W, 0603"
R18: "RES, 0.02, 0.5%, 0.5 W, 1206 sense"
R21 R22 R27: "RES, 100 k, 1%, 0.1 W, 0603"
R23: "RES, 200 k, 1%, 0.1 W, 0603"
R25: "RES, 24.9 k, 1%, 0.1 W, 0603"
R26: "RES, 80.6 k, 1%, 0.1 W, 0603"
TP1 TP2 TP13 TP15 TP18 TP19 TP20 TP23 TP24 TP25 TP26 TP27 TP28 TP29 TP30 TP32 TP33 TP34 TP35 TP36 TP37 TP38 TP39 TP40 TP41 TP42 TP43 TP44 TP45 TP46 TP47 TP50 TP53 TP56: library part Pogopad, "Pad for Pogo Pin Connector"
TP3: "Test Point, Compact, Red, TH"
TP4 TP7 TP8 TP9 TP10 TP11 TP17 TP51 TP54 TP57: "Test Point, Multipurpose, Black, TH"
TP5 TP6 TP12 TP14 TP21 TP22 TP31: library part TESTPOINT, "TEST POINT.  No entry in BOM."
TP16: "Test Point, Compact, White, TH"
TP49 TP52 TP55: "Test Point, Miniature, White, TH"
U1: "BQ500511RHA, RHA0040A"
U2: "4.2V to 5.5V Input, 3A Full Bridge, 2 Channel Analog Demodulation Wireless Power TX-Driver for Wireless Charging Applications, RHB0032E"
ZZ2 ZZ3 ZZ4: library part AssemblyNote
ZZ5 ZZ6 ZZ7: library part "Assembly Note"

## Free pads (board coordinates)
  round 128 hole 128: 0(2596.9,193.1) 0(2596.9,2643.1) 0(5046.9,193.1) 0(5046.9,2643.1)

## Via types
v1: diameter 22, hole 10, Top Layer to Bottom Layer, tented both sides, 206 vias
v2: diameter 19.68, hole 7.87, Top Layer to Bottom Layer, 10 vias
v3: diameter 24, hole 12, Top Layer to Bottom Layer, tented both sides, 6 vias
v4: diameter 26, hole 13, Top Layer to Bottom Layer, tented both sides, 5 vias

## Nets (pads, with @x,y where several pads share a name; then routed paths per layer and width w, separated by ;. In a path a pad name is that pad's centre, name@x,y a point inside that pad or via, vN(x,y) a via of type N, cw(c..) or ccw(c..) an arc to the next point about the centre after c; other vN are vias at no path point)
"FOD THR": R23.1 R27.2 TP30.1 U1.35 | length 345.7
  Top Layer w8: U1.35@866.97,1350 1056,1350 R23.1@1063,1357
  Top Layer w10: R23.1@1067,1372 1127,1372 R27.2@1138,1361 ; R27.2@1132,1370 1135,1373 TP30.1@1135,1440
FOD_CAL: R22.1 R26.2 TP29.1 U1.10 | length 447.3
  Top Layer w10: U1.10@656.42,1477.13 656.42,1671.42 720,1735 720,1765 TP29.1@710,1775 ; TP29.1@715,1770 715,1780 703,1792 703,1835 R26.2@752,1835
